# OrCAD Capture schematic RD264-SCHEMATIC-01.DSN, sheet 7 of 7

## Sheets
7 1: size A3
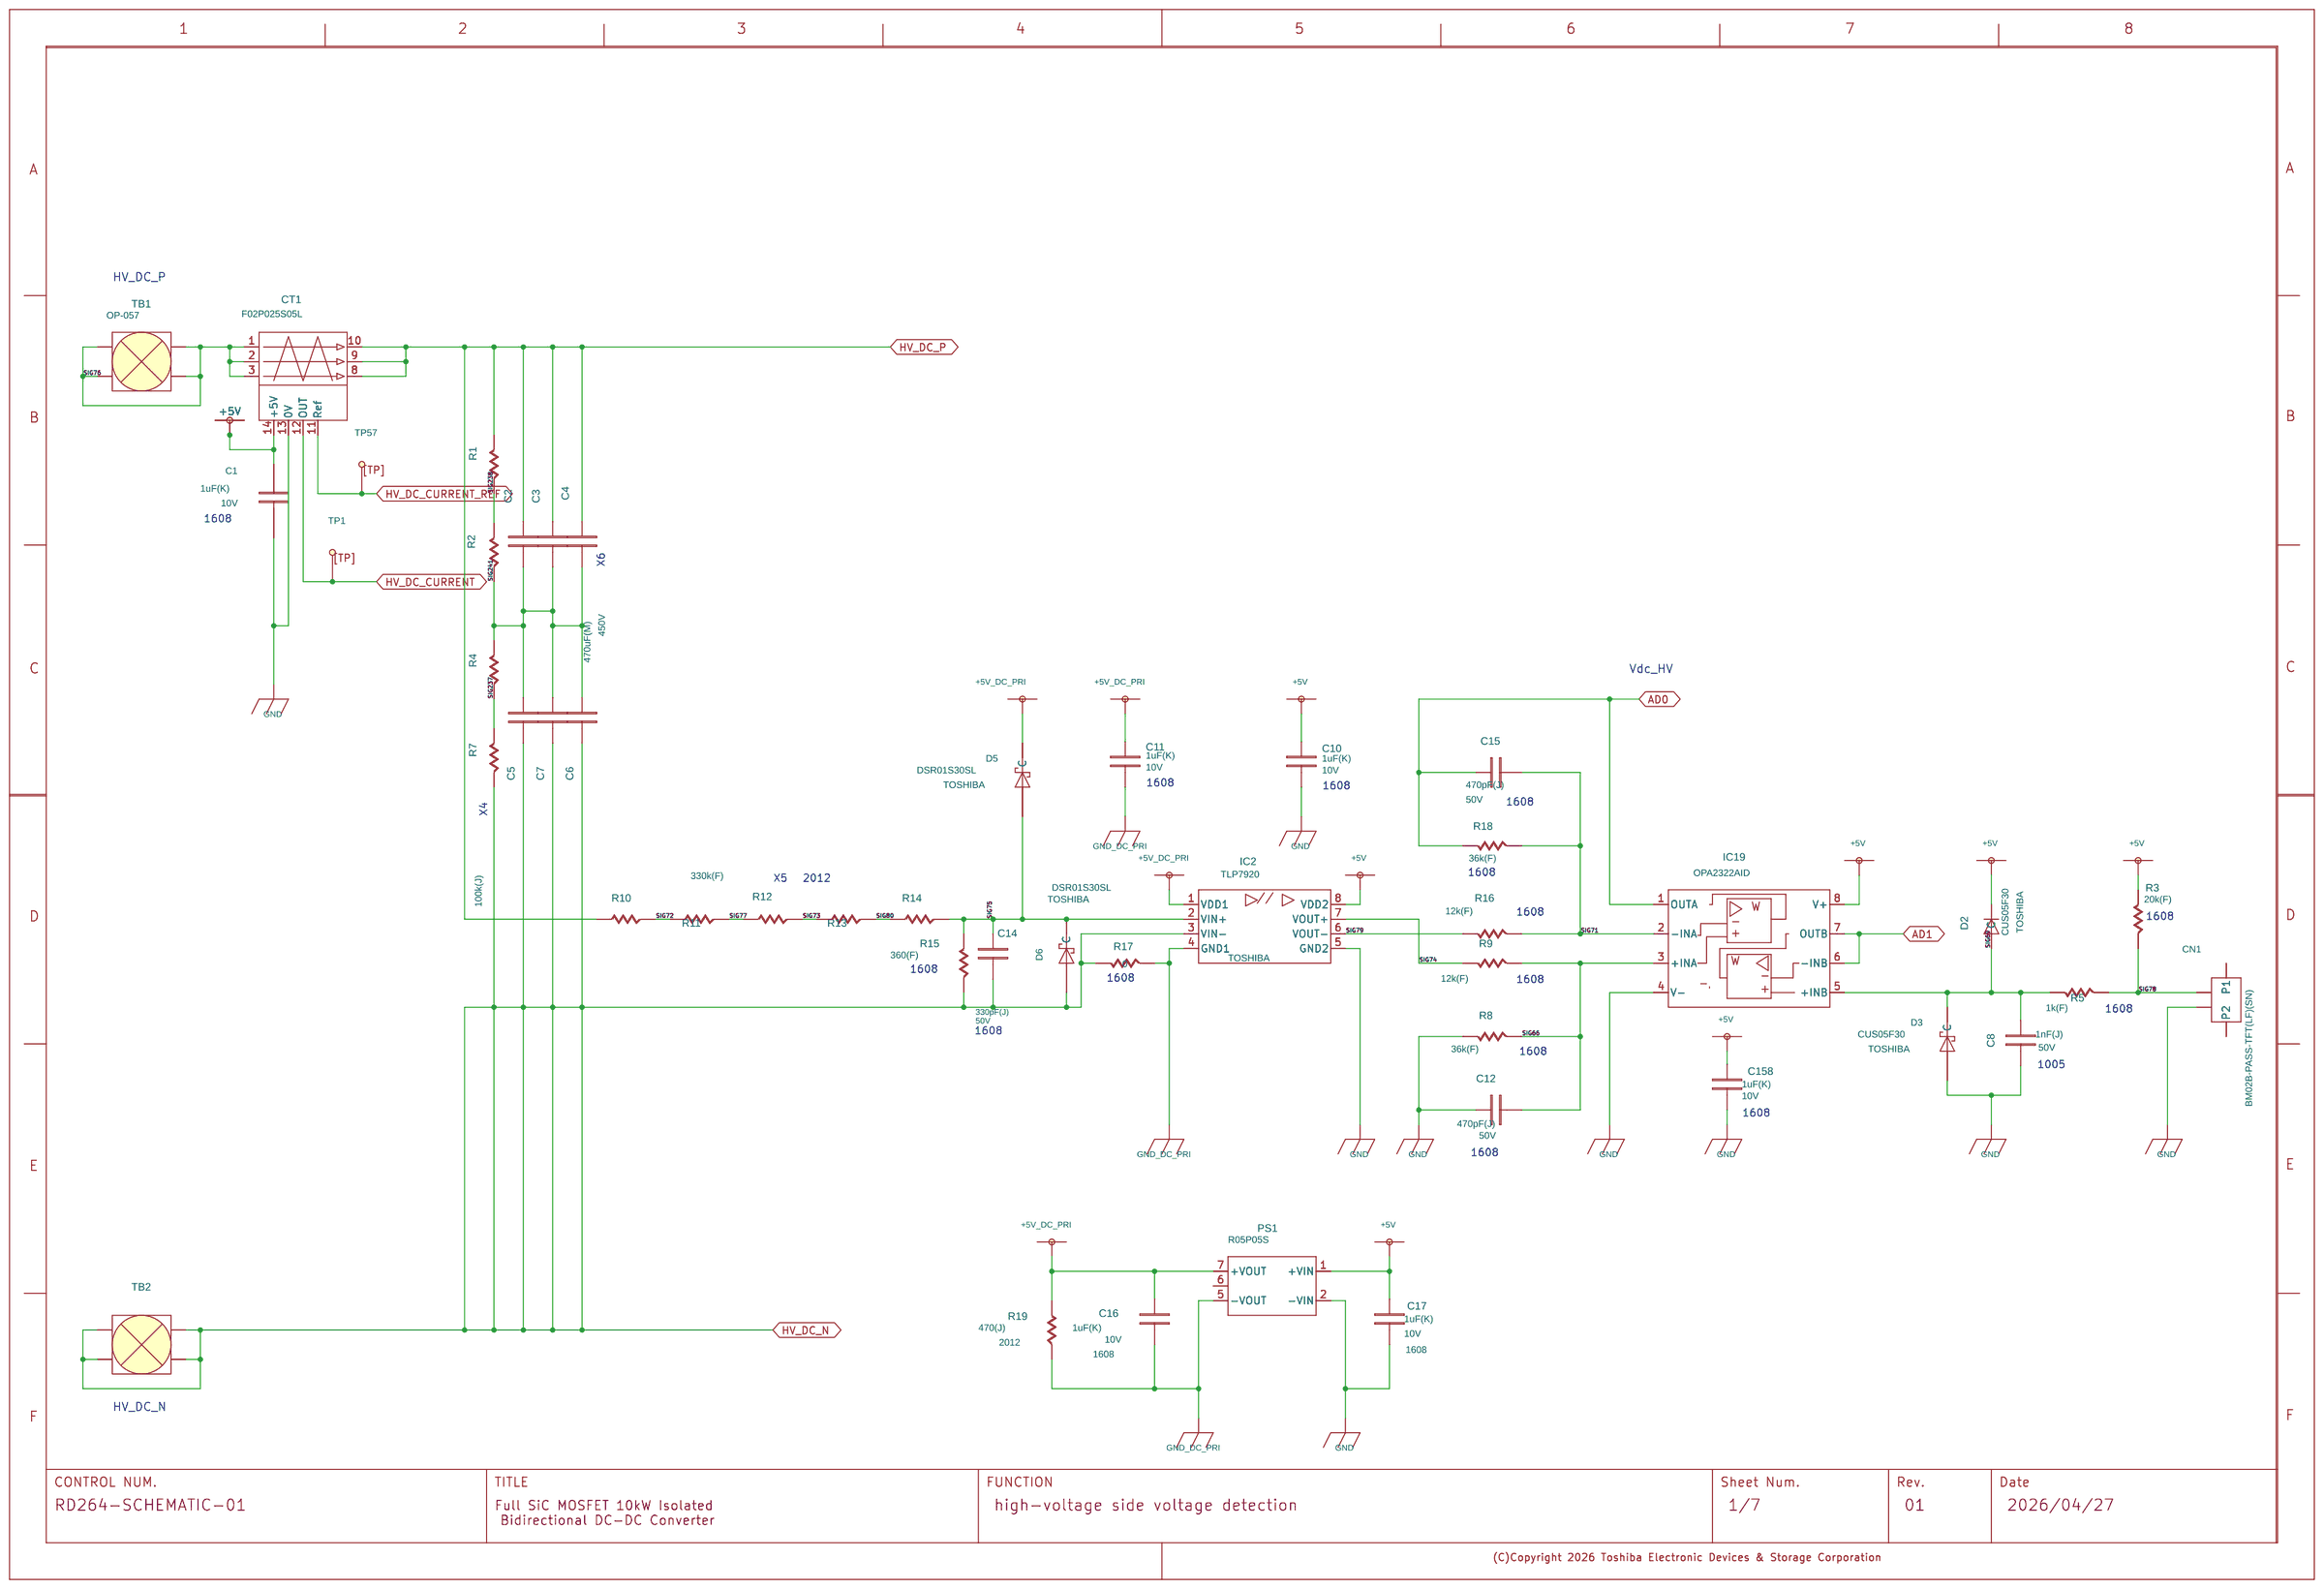
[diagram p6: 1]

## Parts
C1  C
C2  ESMR451VSN471MR40S
C3  ESMR451VSN471MR40S
C4  ESMR451VSN471MR40S
C5  ESMR451VSN471MR40S
C6  ESMR451VSN471MR40S
C7  ESMR451VSN471MR40S
C8  GRM1555C1H102JA01D
C10  GRM188R71A105KA61D
C11  GRM188R71A105KA61D
C12  GRM1885C1H471JA01D
C14  GRM1885C1H331JA01D
C15  GRM1885C1H471JA01D
C16  GRM188R71A105KA61D
C17  GRM188R71A105KA61D
C158  GRM188R71A105KA61D
CN1  BM02B-PASS-TFT(LF)(SN)
CT1  F02P025S05L
D2  CUS05F30
D3  SBD
D5  SBD
D6  SBD
IC2  TLP7920(LF5,TP5)
IC19  OPA2322AIDGKR
PS1  R05P05S
R1  ROX5SJ100K
R2  ROX5SJ100K
R3  RK73H1JTTD2002F
R4  ROX5SJ100K
R5  RK73H1JTTD1001F
R7  ROX5SJ100K
R8  RK73G1JTTD3602F
R9  RK73G1JTTD1202F
R10  RK73H2ATTD3303F
R11  RK73H2ATTD3303F
R12  RK73H2ATTD3303F
R13  RK73H2ATTD3303F
R14  RK73H2ATTD3303F
R15  RK73G1JTTD3600F
R16  RK73G1JTTD1202F
R17  RK73Z1JTTD
R18  RK73G1JTTD3602F
R19  RK73B2ATTD471J
TB1  OP-057
TB2  OP-057
TP1  TP
TP57  TP
U?#6  WAKU_DEF100

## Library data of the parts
C1 = C: COMP: C-GRM188R71A105KA61D; COMPONENTTYPE: 4; VAL1: 1uF(K); VAL2: 10V
C2 = C_v2: COMP: C-ESMR451VSN471MR40S; COMPONENTNAME: C_C.Normal_package; COMPONENTTYPE: 4; FUNCN: C_C.Normal_package; INSTANCENAME: INS17096676; NOTE: 470uF 450V; PART TYPE: Aluminum Capacitor; REFERENCE TEMPLATE: C; SIZE: 1; VAL1: 470uF(M); VAL2: 450V
C3 = C_v2: COMP: C-ESMR451VSN471MR40S; COMPONENTNAME: C_C.Normal_package; COMPONENTTYPE: 4; FUNCN: C_C.Normal_package; INSTANCENAME: INS17096668; NOTE: 470uF 450V; PART TYPE: Aluminum Capacitor; REFERENCE TEMPLATE: C; SIZE: 1; VAL1: 470uF(M); VAL2: 450V
C4 = C_v2: COMP: C-ESMR451VSN471MR40S; COMPONENTNAME: C_C.Normal_package; COMPONENTTYPE: 4; FUNCN: C_C.Normal_package; INSTANCENAME: INS17096660; NOTE: 470uF 450V; PART TYPE: Aluminum Capacitor; REFERENCE TEMPLATE: C; SIZE: 1; VAL1: 470uF(M); VAL2: 450V
C5 = C_v2: COMP: C-ESMR451VSN471MR40S; COMPONENTNAME: C_C.Normal_package; COMPONENTTYPE: 4; FUNCN: C_C.Normal_package; INSTANCENAME: INS17096734; NOTE: 470uF 450V; PART TYPE: Aluminum Capacitor; REFERENCE TEMPLATE: C; SIZE: 1; VAL1: 470uF(M); VAL2: 450V
C6 = C_v2: COMP: C-ESMR451VSN471MR40S; COMPONENTNAME: C_C.Normal_package; COMPONENTTYPE: 4; FUNCN: C_C.Normal_package; INSTANCENAME: INS17096718; NOTE: 470uF 450V; PART TYPE: Aluminum Capacitor; REFERENCE TEMPLATE: C; SIZE: 1; VAL1: 470uF(M); VAL2: 450V
C7 = C_v2: COMP: C-ESMR451VSN471MR40S; COMPONENTNAME: C_C.Normal_package; COMPONENTTYPE: 4; FUNCN: C_C.Normal_package; INSTANCENAME: INS17096726; NOTE: 470uF 450V; PART TYPE: Aluminum Capacitor; REFERENCE TEMPLATE: C; SIZE: 1; VAL1: 470uF(M); VAL2: 450V
C8 = C_v2: COMP: C-GRM1555C1H102JA01D; COMPONENTNAME: C_C.Normal_package; COMPONENTTYPE: 4; FUNCN: C_C.Normal_package; INSTANCENAME: INS17857547; NOTE: 1000pF 50V; PART TYPE: Ceramic Capacitor; REFERENCE TEMPLATE: C; SIZE: 1; VAL1: 1nF(J); VAL2: 50V
C10 = C_v2: COMP: C-GRM188R71A105KA61D; COMPONENTNAME: C_C.Normal_package; COMPONENTTYPE: 4; FUNCN: C_C.Normal_package; INSTANCENAME: INS17096768; NOTE: 1uF 10V; OLDCOMPONENTID: 240; PART TYPE: Ceramic Capacitor; REFERENCE TEMPLATE: C; SIZE: 1; VAL1: 1uF(K); VAL2: 10V
C11 = C_v2: COMP: C-GRM188R71A105KA61D; COMPONENTNAME: C_C.Normal_package; COMPONENTTYPE: 4; FUNCN: C_C.Normal_package; INSTANCENAME: INS17096804; NOTE: 1uF 10V; PART TYPE: Ceramic Capacitor; REFERENCE TEMPLATE: C; SIZE: 1; VAL1: 1uF(K); VAL2: 10V
C12 = C_v2: COMP: C-GRM1885C1H471JA01D; COMPONENTNAME: C_C.Normal_package; COMPONENTTYPE: 4; FUNCN: C_C.Normal_package; INSTANCENAME: INS17096780; NOTE: 470pF 50V; PART TYPE: Ceramic Capacitor; REFERENCE TEMPLATE: C; SIZE: 1; VAL1: 470pF(J); VAL2: 50V
C14 = C_v2: COMP: C-GRM1885C1H331JA01D; COMPONENTNAME: C_C.Normal_package; COMPONENTTYPE: 4; FUNCN: C_C.Normal_package; INSTANCENAME: INS17096988; NOTE: 330pF 50V; PART TYPE: Ceramic Capacitor; REFERENCE TEMPLATE: C; SIZE: 1; VAL1: 330pF(J); VAL2: 50V
C15 = C_v2: COMP: C-GRM1885C1H471JA01D; COMPONENTNAME: C_C.Normal_package; COMPONENTTYPE: 4; FUNCN: C_C.Normal_package; INSTANCENAME: INS17097028; NOTE: 470pF 50V; PART TYPE: Ceramic Capacitor; REFERENCE TEMPLATE: C; SIZE: 1; VAL1: 470pF(J); VAL2: 50V
C16 = C_v2: COMP: C-GRM188R71A105KA61D; COMPONENTNAME: C_C.Normal_package; COMPONENTTYPE: 4; FUNCN: C_C.Normal_package; INSTANCENAME: INS17856707; NOTE: 1uF 10V; PART TYPE: Ceramic Capacitor; REFERENCE TEMPLATE: C; SIZE: 1; SIZECODESMD: 1608; VAL1: 1uF(K); VAL2: 10V
C17 = C_v2: COMP: C-GRM188R71A105KA61D; COMPONENTNAME: C_C.Normal_package; COMPONENTTYPE: 4; FUNCN: C_C.Normal_package; INSTANCENAME: INS17857178; NOTE: 1uF 10V; PART TYPE: Ceramic Capacitor; REFERENCE TEMPLATE: C; SIZE: 1; SIZECODESMD: 1608; VAL1: 1uF(K); VAL2: 10V
C158 = C_v2: COMP: C-GRM188R71A105KA61D; COMPONENTNAME: C_C.Normal_package; COMPONENTTYPE: 4; FUNCN: C_C.Normal_package; INSTANCENAME: INS17335587; NOTE: 1uF 10V; PART TYPE: Ceramic Capacitor; REFERENCE TEMPLATE: C; SIZE: 1; VAL1: 1uF(K); VAL2: 10V
CN1 = BM02B_PASS_TFT_LF__SN: COMP: CN-BM02B-PASS-TFT_LF_SN; COMPONENTNAME: BM02B-PASS-TFT(LF)(SN)_BM02B-PASS-TFT(LF)(SN).Normal_package; COMPONENTTYPE: 4; FUNCN: BM02B-PASS-TFT(LF)(SN)_BM02B-PASS-TFT(LF)(SN).Normal_package; INSTANCENAME: INS17146588; PART TYPE: PA Connector; REFERENCE TEMPLATE: CN; SAVECOUNT: 1; SIZE: 1; UPDATETIME: 14:31:25
CT1 = F02P025S05L: COMP: CT-F02P025S05L; COMPONENTTYPE: 4
D2 = D: COMP: D-CUS05F30; COMPONENTNAME: D_D.Normal_package; COMPONENTTYPE: 4; FUNCN: D_D.Normal_package; INSTANCENAME: INS17146580; USERCOMPTEXT3: TOSHIBA
D3 = SBD: COMP: CUS05F30; COMPONENTTYPE: 4; USERCOMPTEXT3: TOSHIBA; VAL3: CUS05F30
D5 D6 = SBD: COMP: DSR01S30SL; COMPONENTTYPE: 4; USERCOMPTEXT3: TOSHIBA; VAL3: DSR01S30SL
IC2 = TLP7920_LF5: COMP: IC-TLP7920_LF5_TP5; COMPONENTTYPE: 4; USERCOMPTEXT3: TOSHIBA; VAL3: TLP7920
IC19 = OPA2322AIDGKR: COMP: IC-OPA2322AID; COMPONENTTYPE: 4; VAL3: OPA2322AID
PS1 = R05P05S: COMP: PS-R05P05S; COMPONENTTYPE: 4
R1 = R: COMP: R-ROX5SJ100K; COMPONENTNAME: R_R.Normal_package; COMPONENTTYPE: 4; FUNCN: R_R.Normal_package; INSTANCENAME: INS17096650; NOTE: 100kohm 5W; PART TYPE: Resistor; SIZE: 1; VAL1: 100k(J); VAL2: 5w
R2 = R: COMP: R-ROX5SJ100K; COMPONENTNAME: R_R.Normal_package; COMPONENTTYPE: 4; FUNCN: R_R.Normal_package; INSTANCENAME: INS17096684; NOTE: 100kohm 5W; PART TYPE: Resistor; SIZE: 1; VAL1: 100k(J); VAL2: 5w
R3 = R: COMP: R-RK73H1JTTD2002F; COMPONENTNAME: R_R.Normal_package; COMPONENTTYPE: 4; FUNCN: R_R.Normal_package; INSTANCENAME: INS17146572; NOTE: 20kohm 0.1W; VAL1: 20k(F); VAL2: 100mw
R4 = R: COMP: R-ROX5SJ100K; COMPONENTNAME: R_R.Normal_package; COMPONENTTYPE: 4; FUNCN: R_R.Normal_package; INSTANCENAME: INS17096742; NOTE: 100kohm 5W; PART TYPE: Resistor; SIZE: 1; VAL1: 100k(J); VAL2: 5w
R5 = R: COMP: R-RK73H1JTTD1001F; COMPONENTNAME: R_R.Normal_package; COMPONENTTYPE: 4; FUNCN: R_R.Normal_package; INSTANCENAME: INS17858314; NOTE: 1.0kohm 0.1W; PART TYPE: Resistor SMD; SIZE: 1; VAL1: 1k(F); VAL2: 125mw
R7 = R: COMP: R-ROX5SJ100K; COMPONENTNAME: R_R.Normal_package; COMPONENTTYPE: 4; FUNCN: R_R.Normal_package; INSTANCENAME: INS17096788; NOTE: 100kohm 5W; PART TYPE: Resistor; SIZE: 1; VAL1: 100k(J); VAL2: 5w
R8 = R: COMP: R-RK73G1JTTD3602F; COMPONENTNAME: R_R.Normal_package; COMPONENTTYPE: 4; FUNCN: R_R.Normal_package; INSTANCENAME: INS17096812; NOTE: 36kohm 0.1W; VAL1: 36k(F); VAL2: 100mw
R9 = R: COMP: R-RK73G1JTTD1202F; COMPONENTNAME: R_R.Normal_package; COMPONENTTYPE: 4; FUNCN: R_R.Normal_package; INSTANCENAME: INS17096836; NOTE: 12kohm 0.1W; VAL1: 12k(F); VAL2: 100mw
R10 = R: COMP: R-RK73H2ATTD3303F; COMPONENTNAME: R_R.Normal_package; COMPONENTTYPE: 4; FUNCN: R_R.Normal_package; INSTANCENAME: INS17779029; NOTE: 330kohm 0.25W; PART NUMBER: TMP-977; PART TYPE: Resistor SMD; VAL1: 330k(F); VAL2: 250mw
R11 = R: COMP: R-RK73H2ATTD3303F; COMPONENTNAME: R_R.Normal_package; COMPONENTTYPE: 4; FUNCN: R_R.Normal_package; INSTANCENAME: INS17779073; NOTE: 330kohm 0.25W; PART NUMBER: TMP-977; PART TYPE: Resistor SMD; VAL1: 330k(F); VAL2: 250mw
R12 = R: COMP: R-RK73H2ATTD3303F; COMPONENTNAME: R_R.Normal_package; COMPONENTTYPE: 4; FUNCN: R_R.Normal_package; INSTANCENAME: INS17779223; NOTE: 330kohm 0.25W; PART NUMBER: TMP-977; PART TYPE: Resistor SMD; VAL1: 330k(F); VAL2: 250mw
R13 = R: COMP: R-RK73H2ATTD3303F; COMPONENTNAME: R_R.Normal_package; COMPONENTTYPE: 4; FUNCN: R_R.Normal_package; INSTANCENAME: INS17779250; NOTE: 330kohm 0.25W; PART NUMBER: TMP-977; PART TYPE: Resistor SMD; VAL1: 330k(F); VAL2: 250mw
R14 = R: COMP: R-RK73H2ATTD3303F; COMPONENTNAME: R_R.Normal_package; COMPONENTTYPE: 4; FUNCN: R_R.Normal_package; INSTANCENAME: INS17779350; NOTE: 330kohm 0.25W; PART NUMBER: TMP-977; PART TYPE: Resistor SMD; VAL1: 330k(F); VAL2: 250mw
R15 = R: COMP: R-RK73G1JTTD3600F; COMPONENTNAME: R_R.Normal_package; COMPONENTTYPE: 4; FUNCN: R_R.Normal_package; INSTANCENAME: INS17096996; NOTE: 360ohm 0.1W; VAL1: 360(F); VAL2: 100mw
R16 = R: COMP: R-RK73G1JTTD1202F; COMPONENTNAME: R_R.Normal_package; COMPONENTTYPE: 4; FUNCN: R_R.Normal_package; INSTANCENAME: INS17096888; NOTE: 12kohm 0.1W; VAL1: 12k(F); VAL2: 100mw
R17 = R: COMP: R-RK73Z1JTTD; COMPONENTNAME: R_R.Normal_package; COMPONENTTYPE: 4; FUNCN: R_R.Normal_package; INSTANCENAME: INS17097020; NOTE: 0ohm 0.1W; PART TYPE: Resistor SMD; SIZE: 1; VAL1: 0
R18 = R: COMP: R-RK73G1JTTD3602F; COMPONENTNAME: R_R.Normal_package; COMPONENTTYPE: 4; FUNCN: R_R.Normal_package; INSTANCENAME: INS17096966; NOTE: 36kohm 0.1W; VAL1: 36k(F); VAL2: 100mw
R19 = R: COMP: R-RK73B2ATTD471J; COMPONENTNAME: R_R.Normal_package; COMPONENTTYPE: 4; FUNCN: R_R.Normal_package; INSTANCENAME: INS17417018; NOTE: 470ohm 0.25W; PART TYPE: Resistor SMD; SIZE: 1; SIZECODESMD: 2012; VAL1: 470(J); VAL2: 250mw
TB1 = OP_057: COMP: TB-OP-057; COMPONENTNAME: OP-057_OP-057.Normal_package; COMPONENTTYPE: 4; FUNCN: OP-057_OP-057.Normal_package; INSTANCENAME: INS17363560; PART NUMBER: TMP-784; PART TYPE: Terminal Block; REFERENCE TEMPLATE: TB; SAVECOUNT: 1; UPDATETIME: 14:31:25
TB2 = OP_057: COMP: TB-OP-057; COMPONENTNAME: OP-057_OP-057.Normal_package; COMPONENTTYPE: 4; FUNCN: OP-057_OP-057.Normal_package; INSTANCENAME: INS17363646; PART NUMBER: TMP-784; PART TYPE: Terminal Block; REFERENCE TEMPLATE: TB; SAVECOUNT: 1; UPDATETIME: 14:31:25
TP1 TP57 = TP: COMP: TP-HK-3-G; COMPONENTTYPE: 4; VAL3: HK-3-G
U?#6 = WAKU_DEF100: COMPONENTTYPE: 2; DATE: 2026/04/27; DRAWINGNUMBER: RD264-SCHEMATIC-01; FUNCTION: high-voltage side voltage detection; REVISION: 01; SHEETNUMBER: 1/7; SHTSAVECOUNT: 16; TITLE: Full SiC MOSFET 10kW Isolated / Bidirectional DC-DC Converter; UPDATEDATE: 2026.4.27; UPDATETIME: 14:22:34

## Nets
+5V: C1.1 C10.1 C17.1 C158.1 CT1.14(+5V) D2.K(C) IC2.8(VDD2) IC19.8(V+) PS1.1(+VIN) R3.1 ; also on sheet 1 2 3 4 5 6
+5V_DC_PRI: C11.1 C16.1 D5.K(C) IC2.1(VDD1) PS1.7(+VOUT) R19.1
GND: C1.2 C8.2 C10.2 C12.1 C17.2 C158.2 CN1.2 CT1.13(0V) D3.A IC2.5(GND2) IC19.4(V-) PS1.2(-VIN) R8.1 ; also on sheet 1 2 3 4 5 6
GND_DC_PRI: C11.2 C16.2 IC2.4(GND1) PS1.5(-VOUT) R17.2 R19.2
AD0: C15.1 IC19.1(OUTA) R18.1 ; also on sheet 1
AD1: IC19.6(-INB) IC19.7(OUTB) ; also on sheet 1
HV_DC_CURRENT: CT1.12(OUT) TP1.1 ; also on sheet 2
HV_DC_CURRENT_REF: CT1.11(Ref) TP57.1 ; also on sheet 2
HV_DC_N: C5.2 C6.2 C7.2 C14.2 D6.A IC2.3(VIN-) R7.2 R15.2 R17.1 TB2.1 TB2.2 TB2.3 TB2.4 ; also on sheet 5 6
HV_DC_P: C2.1 C3.1 C4.1 CT1.8 CT1.9 CT1.10 R1.1 R10.1 ; also on sheet 5 6
SIG66: C12.2 IC19.3(+INA) R8.2 R9.2
SIG69: C8.1 D2.A D3.K(C) IC19.5(+INB) R5.1
SIG71: C15.2 IC19.2(-INA) R16.2 R18.2
SIG72: R10.2 R11.1
SIG73: R12.2 R13.1
SIG74: IC2.7(VOUT+) R9.1
SIG75: C14.1 D5.A D6.K(C) IC2.2(VIN+) R14.2 R15.1
SIG76: CT1.1 CT1.2 CT1.3 TB1.1 TB1.2 TB1.3 TB1.4
SIG77: R11.2 R12.1
SIG78: CN1.1 R3.2 R5.2
SIG79: IC2.6(VOUT-) R16.1
SIG80: R13.2 R14.1
SIG237: R4.2 R7.1
SIG238: R1.2 R2.1
SIG241: C2.2 C3.2 C4.2 C5.1 C6.1 C7.1 R2.2 R4.1

Not connected (* = marked no-connect by the designer): CN1 NC1(P1) NC2(P2); PS1 6

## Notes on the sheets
sheet 7
- HV_DC_P
- 1608
- X6
- Vdc_HV
- 1608
- 1608
- 1608
- X4
- X5
- 2012
- 1608
- 1608
- 1608
- 1608
- 1608
- 1608
- 1608
- 1608
- 1608
- 1005
- 1608
- 1608
- HV_DC_N
